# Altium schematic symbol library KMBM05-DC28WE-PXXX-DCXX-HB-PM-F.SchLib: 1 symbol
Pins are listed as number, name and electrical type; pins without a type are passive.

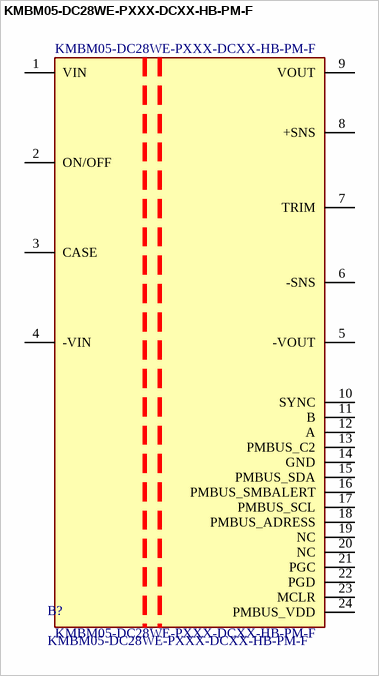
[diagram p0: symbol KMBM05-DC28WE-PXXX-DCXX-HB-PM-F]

## KMBM05-DC28WE-PXXX-DCXX-HB-PM-F
designator B?
9-70Vin XXVout XXXW Isolated Half Brick with Flanged Option; MFG: KOLT
footprint KMBM05-DC28WE-PXXX-DCXX-HB-PM-F
pins: 1 VIN, 2 ON/OFF, 3 CASE, 4 -VIN, 5 -VOUT, 6 -SNS, 7 TRIM, 8 +SNS, 9 VOUT, 10 SYNC, 11 B, 12 A, 13 PMBUS_C2, 14 GND, 15 PMBUS_SDA, 16 PMBUS_SMBALERT, 17 PMBUS_SCL, 18 PMBUS_ADRESS, 19 NC, 20 NC, 21 PGC, 22 PGD, 23 MCLR, 24 PMBUS_VDD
